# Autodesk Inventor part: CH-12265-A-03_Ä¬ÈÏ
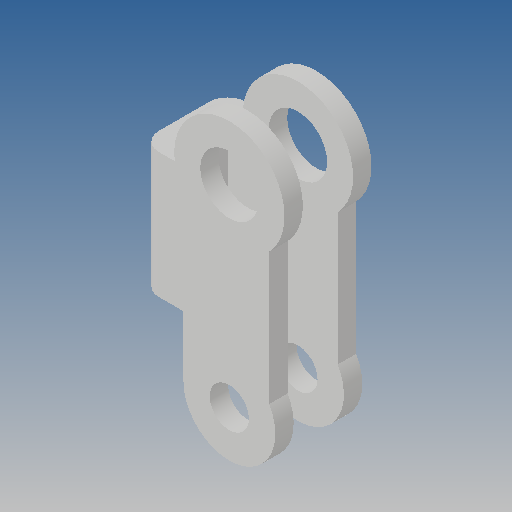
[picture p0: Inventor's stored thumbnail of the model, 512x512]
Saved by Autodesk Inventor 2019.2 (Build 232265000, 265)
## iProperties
Created: 2010-06
Part Number: CH-12265-A-03_Ä¬ÈÏ
Material: Ogólny
Document SubType Name: Modeling
Designer: CADENGINEERING4
Density: 1 g/cm^3
Appearance: Domyślna
Author: CADENGINEERING4
Revision Number: ÈÎºÎ
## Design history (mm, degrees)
feature "NONE"
node "Bryła1"
